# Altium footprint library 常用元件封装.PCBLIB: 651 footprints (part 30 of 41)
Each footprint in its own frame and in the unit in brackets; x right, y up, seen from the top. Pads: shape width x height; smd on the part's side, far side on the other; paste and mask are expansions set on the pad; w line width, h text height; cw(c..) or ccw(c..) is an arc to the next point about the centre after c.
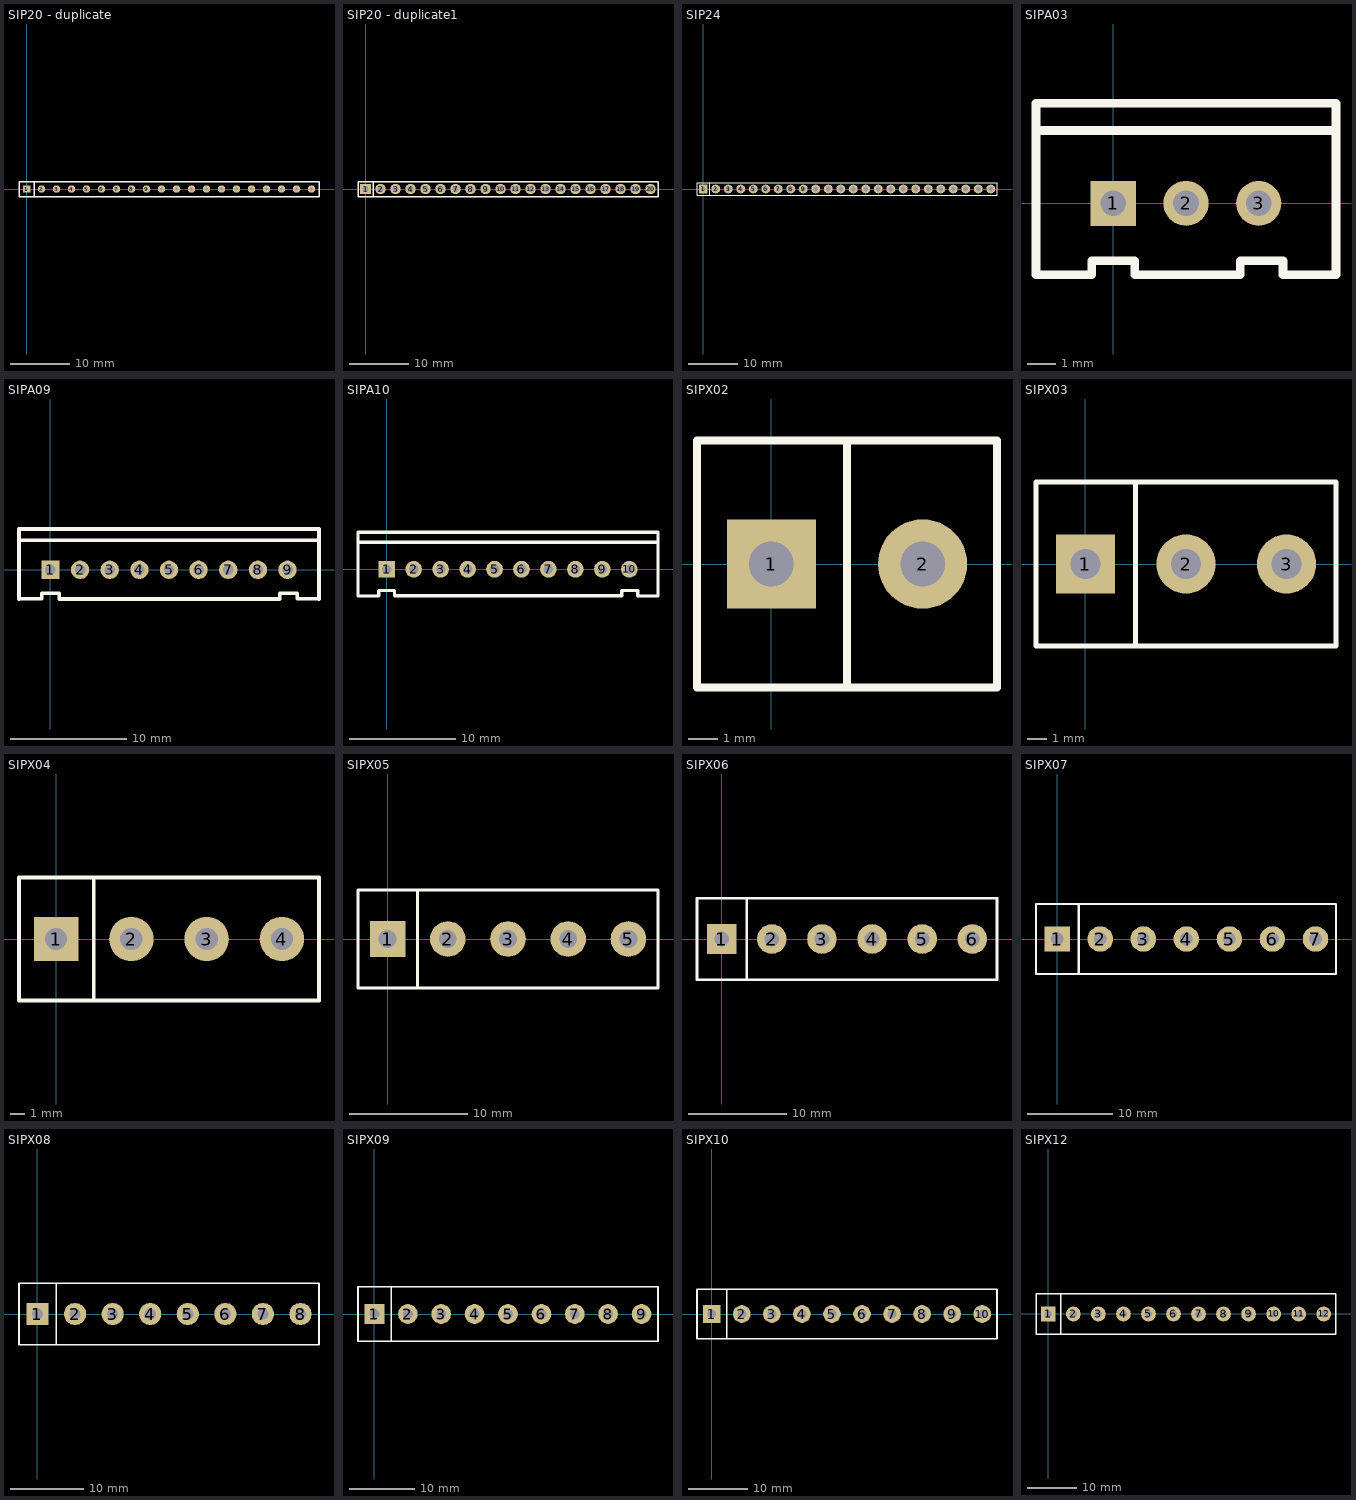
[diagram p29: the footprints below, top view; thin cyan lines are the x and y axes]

## SIP20 - duplicate [mm]
pads (20):
  rect 1.27x1.27 hole 0.5: 1(0,0)
  round 1.27 hole 0.5: 2(2.54,0) 3(5.08,0) 4(7.62,0) 5(10.16,0) 6(12.7,0) 7(15.24,0) 8(17.78,0) 9(20.32,0) 10(22.86,0) 11(25.4,0) 12(27.94,0) 13(30.48,0) 14(33.02,0) 15(35.56,0) 16(38.1,0) 17(40.64,0) 18(43.18,0) 19(45.72,0) 20(48.26,0)
TopOverlay:
  lines w0.254: 1.27,-1.27 1.27,1.27 ; -1.27,-1.27 49.53,-1.27 49.53,1.27 -1.27,1.27 -1.27,-1.27

## SIP20 - duplicate1 [mil]
pads (20):
  rect 70x70 hole 39: 1(0,0)
  round 70 hole 39: 2(100,0) 3(200,0) 4(300,0) 5(400,0) 6(500,0) 7(600,0) 8(700,0) 9(800,0) 10(900,0) 11(1000,0) 12(1100,0) 13(1200,0) 14(1300,0) 15(1400,0) 16(1500,0) 17(1600,0) 18(1700,0) 19(1800,0) 20(1900,0)
TopOverlay:
  lines w10: 50,-50 50,50 ; -50,-50 1950,-50 1950,50 -50,50 -50,-50

## SIP24 [mil]
pads (24):
  rect 70x70 hole 39: 1(0,0)
  round 70 hole 39: 2(100,0) 3(200,0) 4(300,0) 5(400,0) 6(500,0) 7(600,0) 8(700,0) 9(800,0) 10(900,0) 11(1000,0) 12(1100,0) 13(1200,0) 14(1300,0) 15(1400,0) 16(1500,0) 17(1600,0) 18(1700,0) 19(1800,0) 20(1900,0) 21(2000,0) 22(2100,0) 23(2200,0) 24(2300,0)
TopOverlay:
  lines w10: 50,-50 50,50 ; -50,-50 -50,50 2350,50 2350,-50 -50,-50

## SIPA03 [mil]
pads (3):
  rect 62x62 hole 35.43: 1(0,0)
  round 62 hole 35.43: 2(100,0) 3(200,0)
TopOverlay:
  lines w11.81: -106.3,-98.42 -29.53,-98.42 -29.53,-78.74 29.53,-78.74 29.53,-98.42 ; 174.41,-98.42 174.41,-78.74 233.47,-78.74 233.47,-98.42 306.3,-98.42
  lines w12: -106.3,-98.42 -106.3,137.79 304.72,137.79 ; -106.3,100 304.72,100 ; 29.53,-98.42 174.41,-98.42 ; 306.3,-98.42 306.3,137.79

## SIPA09 [mil]
pads (9):
  rect 62x62 hole 35.43: 1(0,0)
  round 62 hole 35.43: 2(100,0) 3(200,0) 4(300,0) 5(400,0) 6(500,0) 7(600,0) 8(700,0) 9(800,0)
TopOverlay:
  lines w11.81: -106.3,-98.42 -29.53,-98.42 -29.53,-78.74 29.53,-78.74 29.53,-98.42 ; 774.41,-98.42 774.41,-78.74 833.47,-78.74 833.47,-98.42 906.3,-98.42
  lines w12: -106.3,-98.42 -106.3,137.79 904.72,137.79 ; -106.3,100 904.72,100 ; 29.53,-98.42 774.41,-98.42 ; 906.3,-98.42 906.3,137.79

## SIPA10 [mil]
pads (10):
  rect 62x62 hole 35.43: 1(0,0)
  round 62 hole 35.43: 2(100,0) 3(200,0) 4(300,0) 5(400,0) 6(500,0) 7(600,0) 8(700,0) 9(800,0) 10(900,0)
TopOverlay:
  lines w11.81: -106.3,-98.42 -29.53,-98.42 -29.53,-78.74 29.53,-78.74 29.53,-98.42 ; 872.05,-98.42 872.05,-78.74 931.1,-78.74 931.1,-98.42 1005.32,-98.42
  lines w12: -106.3,-98.42 -106.3,137.79 1006.3,137.79 1006.3,-98.42 ; -106.3,100 1006.3,100 ; 29.53,-98.42 872.05,-98.42

## SIPX02 [mm]
pads (2):
  rect 3x3 hole 1.5: 1(0,0)
  round 3 hole 1.5: 2(5.08,0)
TopOverlay:
  lines w0.254: 2.54,-4.15 2.54,4.15 ; -2.5,-4.15 7.58,-4.15 7.58,4.15 -2.5,4.15 -2.5,-4.15

## SIPX03 [mm]
pads (3):
  rect 3x3 hole 1.5: 1(0,0)
  round 3 hole 1.5: 2(5.08,0) 3(10.16,0)
TopOverlay:
  lines w0.254: 2.54,-4.15 2.54,4.15 ; -2.5,-4.15 -2.5,4.15 12.66,4.15 12.66,-4.15 -2.5,-4.15

## SIPX04 [mm]
pads (4):
  rect 3x3 hole 1.5: 1(0,0)
  round 3 hole 1.5: 2(5.08,0) 3(10.16,0) 4(15.24,0)
TopOverlay:
  lines w0.254: 2.54,-4.15 2.54,4.15 ; -2.5,-4.15 -2.5,4.15 17.74,4.15 17.74,-4.15 -2.5,-4.15

## SIPX05 [mm]
pads (5):
  rect 3x3 hole 1.5: 1(0,0)
  round 3 hole 1.5: 2(5.08,0) 3(10.16,0) 4(15.24,0) 5(20.32,0)
TopOverlay:
  lines w0.254: 2.54,-4.15 2.54,4.15 ; -2.5,-4.15 22.82,-4.15 22.82,4.15 -2.5,4.15 -2.5,-4.15

## SIPX06 [mm]
pads (6):
  rect 3x3 hole 1.5: 1(0,0)
  round 3 hole 1.5: 2(5.08,0) 3(10.16,0) 4(15.24,0) 5(20.32,0) 6(25.4,0)
TopOverlay:
  lines w0.254: 2.54,-4.15 2.54,4.15 ; -2.5,-4.15 -2.5,4.15 27.9,4.15 27.9,-4.15 -2.5,-4.15

## SIPX07 [mm]
pads (7):
  rect 3x3 hole 1.5: 1(0,0)
  round 3 hole 1.5: 2(5.08,0) 3(10.16,0) 4(15.24,0) 5(20.32,0) 6(25.4,0) 7(30.48,0)
TopOverlay:
  lines w0.254: 2.54,-4.15 2.54,4.15 ; -2.5,-4.15 32.9,-4.15 32.9,4.15 -2.5,4.15 -2.5,-4.15

## SIPX08 [mm]
pads (8):
  rect 3x3 hole 1.5: 1(0,0)
  round 3 hole 1.5: 2(5.08,0) 3(10.16,0) 4(15.24,0) 5(20.32,0) 6(25.4,0) 7(30.48,0) 8(35.56,0)
TopOverlay:
  lines w0.254: 2.54,-4.15 2.54,4.15 ; -2.5,-4.15 38.06,-4.15 38.06,4.15 -2.5,4.15 -2.5,-4.15

## SIPX09 [mm]
pads (9):
  rect 3x3 hole 1.5: 1(0,0)
  round 3 hole 1.5: 2(5.08,0) 3(10.16,0) 4(15.24,0) 5(20.32,0) 6(25.4,0) 7(30.48,0) 8(35.56,0) 9(40.64,0)
TopOverlay:
  lines w0.254: 2.54,-4.15 2.54,4.15 ; -2.5,-4.15 43.14,-4.15 43.14,4.15 -2.5,4.15 -2.5,-4.15

## SIPX10 [mm]
pads (10):
  rect 3x3 hole 1.5: 1(0,0)
  round 3 hole 1.5: 2(5.08,0) 3(10.16,0) 4(15.24,0) 5(20.32,0) 6(25.4,0) 7(30.48,0) 8(35.56,0) 9(40.64,0) 10(45.72,0)
TopOverlay:
  lines w0.254: 2.54,-4.15 2.54,4.15 ; -2.5,-4.15 48.22,-4.15 48.22,4.15 -2.5,4.15 -2.5,-4.15

## SIPX12 [mm]
pads (12):
  rect 3x3 hole 1.5: 1(0,0)
  round 3 hole 1.5: 2(5.08,0) 3(10.16,0) 4(15.24,0) 5(20.32,0) 6(25.4,0) 7(30.48,0) 8(35.56,0) 9(40.64,0) 10(45.72,0) 11(50.8,0) 12(55.88,0)
TopOverlay:
  lines w0.254: 2.54,-4.15 2.54,4.15 ; -2.5,-4.15 58.38,-4.15 58.38,4.15 -2.5,4.15 -2.5,-4.15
